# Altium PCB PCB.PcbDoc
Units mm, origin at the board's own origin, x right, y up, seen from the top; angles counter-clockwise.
Board outline 41 x 25.36 mm, 2 copper layers (TOP, BOTTOM), stack 1.586 mm thick; 38 components, 21 nets, 105 pads, 68 vias.
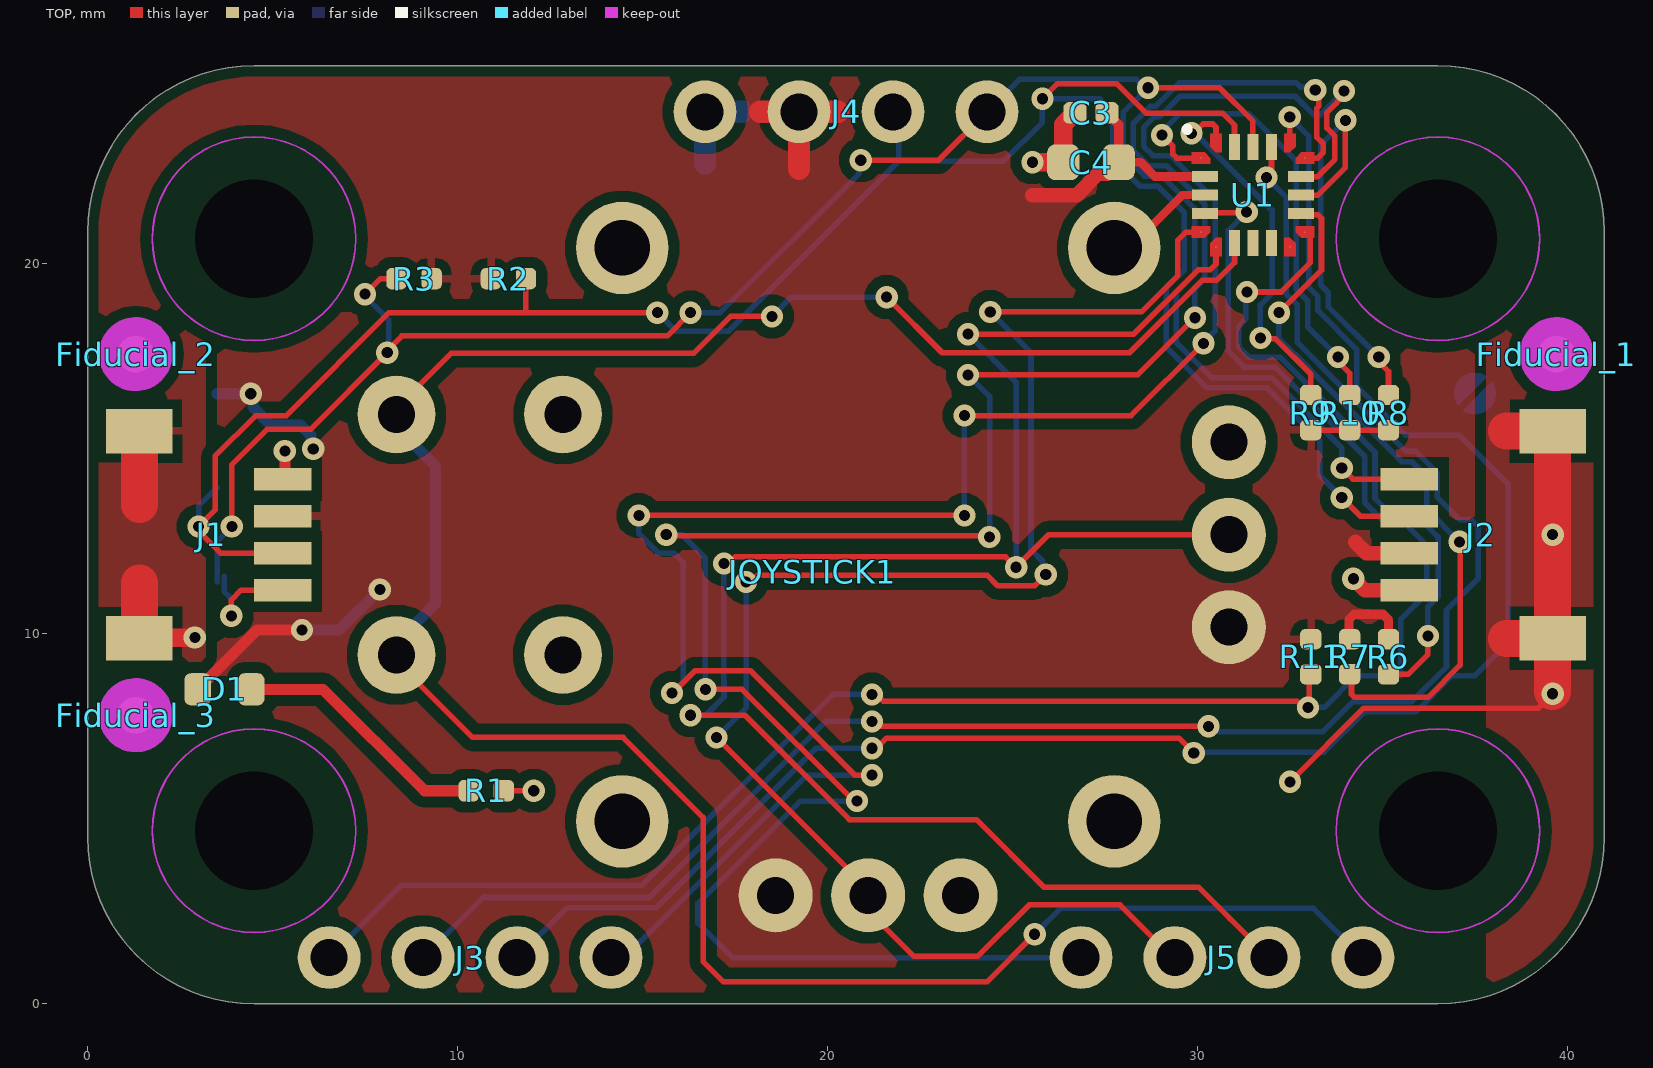
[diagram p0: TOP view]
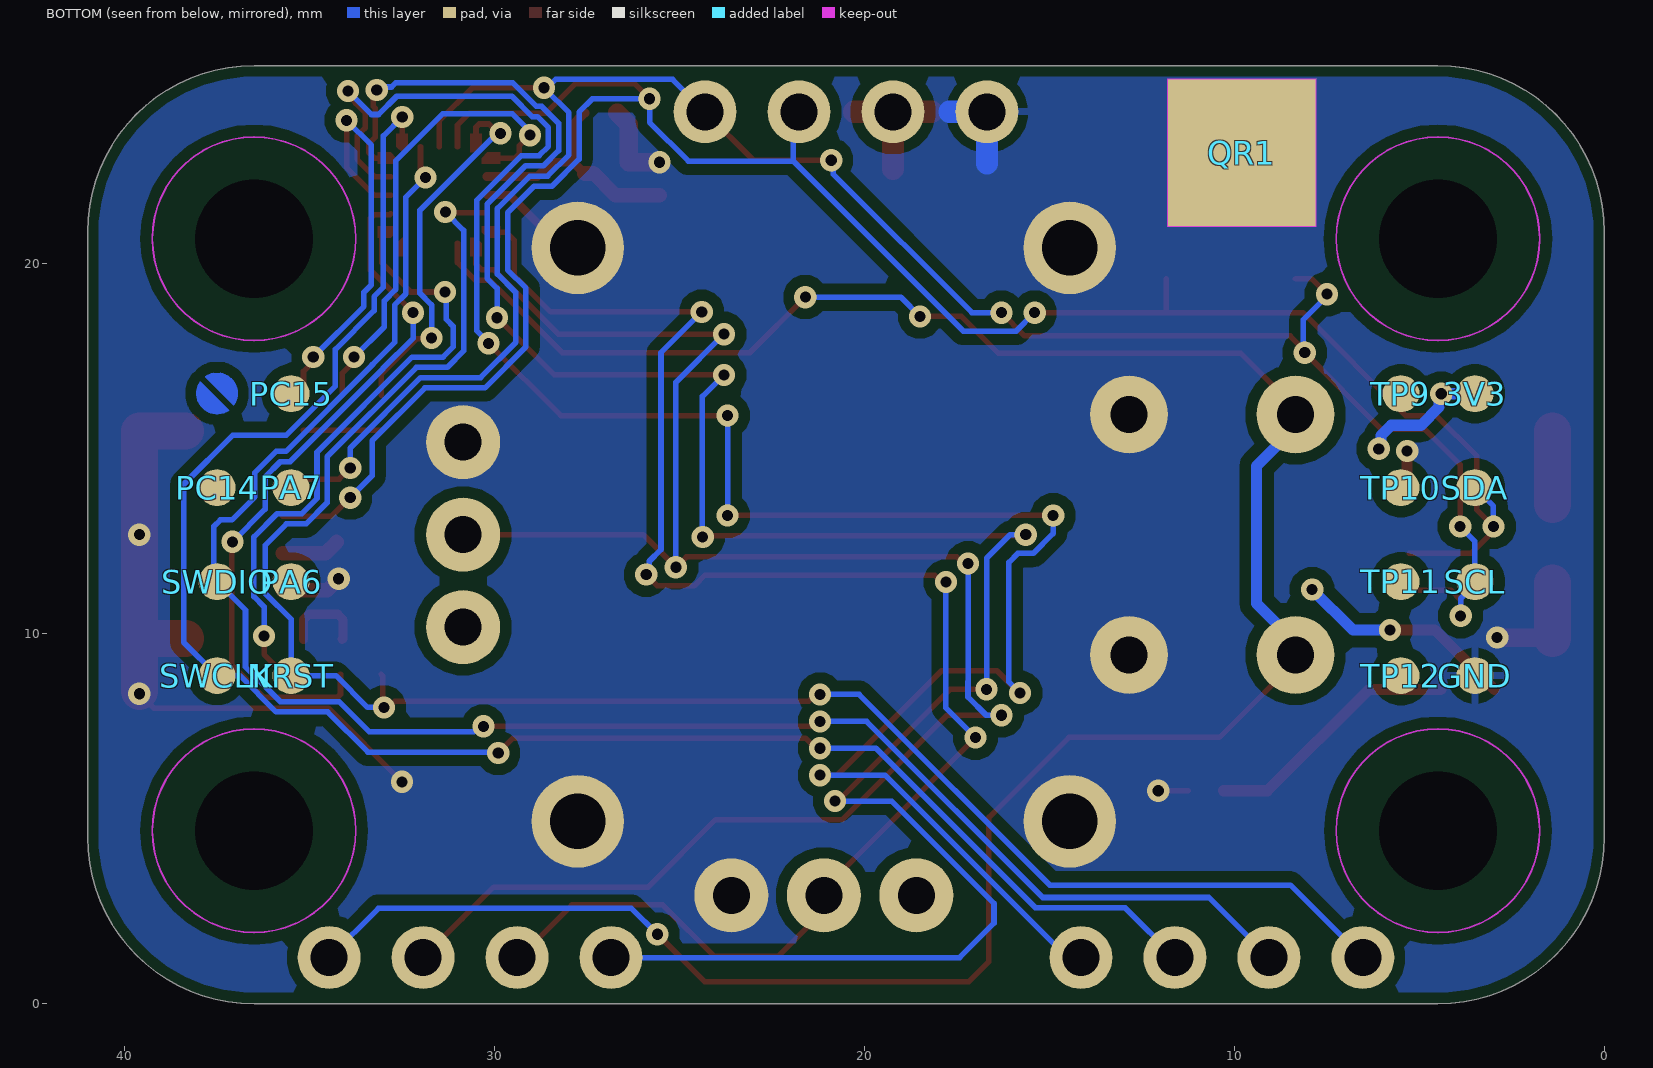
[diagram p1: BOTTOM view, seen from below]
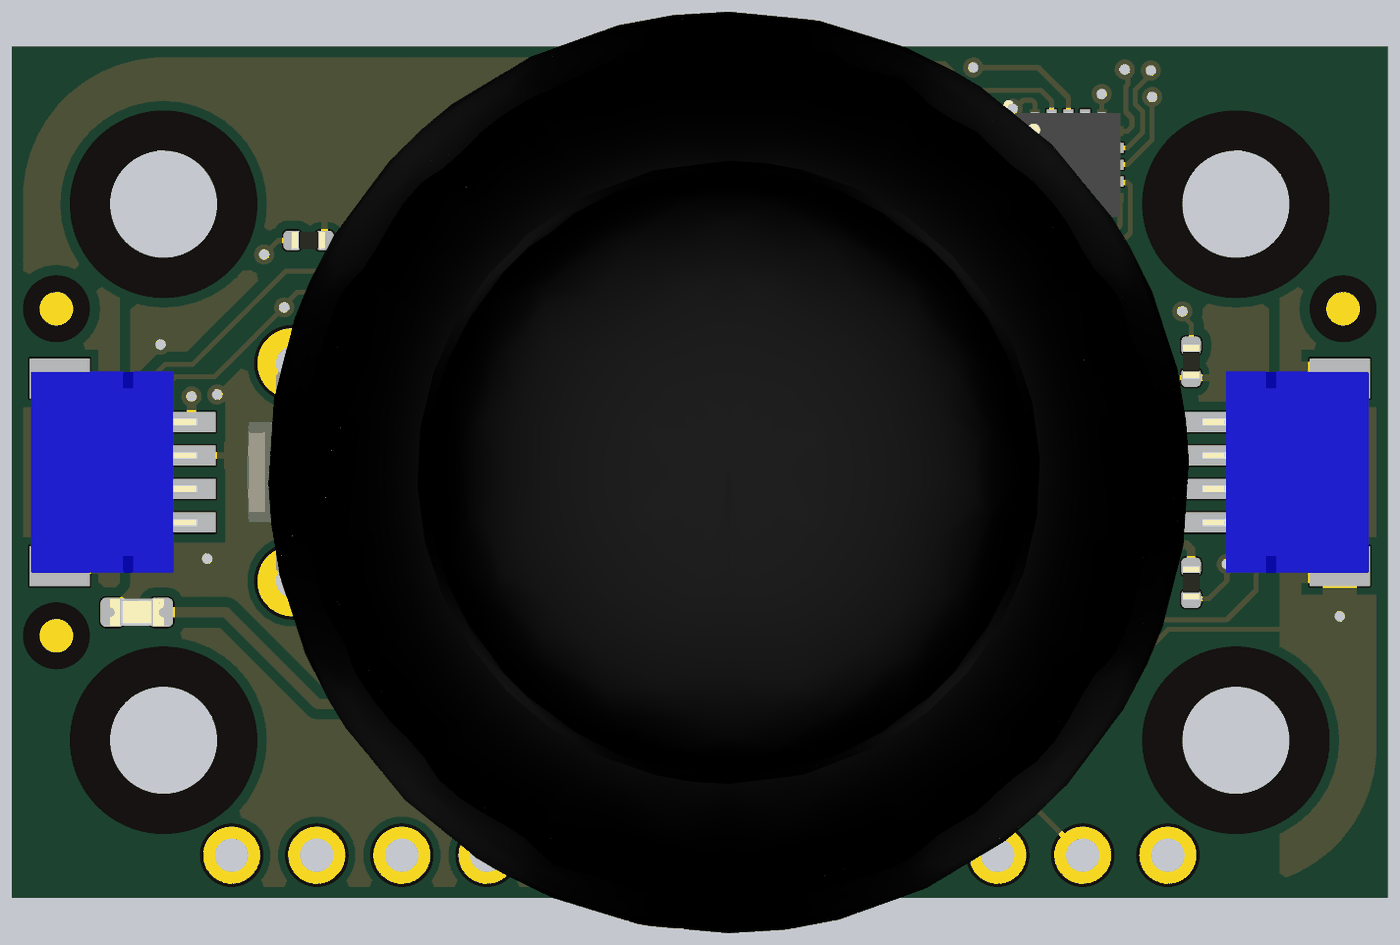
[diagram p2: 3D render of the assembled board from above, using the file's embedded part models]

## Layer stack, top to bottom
Top Solder: solder mask 0.01, Solder Resist, Dk 3.5
TOP: signal copper 0.018
Dielectric: core 1.55, FR-4, Dk 4.8
BOTTOM: signal copper 0.018
Bottom Solder: solder mask 0.01, Solder Resist, Dk 3.5

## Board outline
0,4.5 ccw(c4.5,4.5) 4.5,0 36.5,0 ccw(c36.5,4.5) 41,4.5 41,20.86 ccw(c36.5,20.86) 36.5,25.36 4.5,25.36 ccw(c4.5,20.86) 0,20.86

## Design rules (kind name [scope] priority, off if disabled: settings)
BoardOutlineClearance Mousebites [(ObjectKind = 'Pad') And (Name = 'Free-MOUSEBITE')] p1: gap=0 ignorepadtopadclearanceinfootprint=FALSE
BoardOutlineClearance Silks [(OnLayer('Top Overlay') OR OnLayer('Bottom Overlay'))] p2: gap=0 ignorepadtopadclearanceinfootprint=FALSE
BoardOutlineClearance [All] p3: gap=0.3 ignorepadtopadclearanceinfootprint=FALSE
Clearance COPPER_0.3mm [All] p1: gap=0.127 ignorepadtopadclearanceinfootprint=FALSE except(0.3: Arc-Fill Arc-Poly Arc-Region Track-Fill Track-Poly Track-Region SMDPad-Fill SMDPad-Poly SMDPad-Region THPad-Fill THPad-Poly THPad-Region Via-Fill Via-Poly Via-Region Fill-Fill Fill-Poly Fill-Region Poly-Poly Poly-Region Region-Region)
Clearance "Generic clearance 0.15mm" [All] p2: gap=0.15 ignorepadtopadclearanceinfootprint=FALSE
ComponentClearance [All] p1: gap=0.2 collisioncheckmode=3 verticalgap=0 showdistances=TRUE
DiffPairsRouting USB [InDifferentialPairClass('USB')] p1: maxlimit=0.15 minlimit=0.15 mostfreqgap=0.15 toplayer_minwidth=0.15 toplayer_maxwidth=0.21 toplayer_prefwidth=0.2 bottomlayer_minwidth=0.15 bottomlayer_maxwidth=0.21 bottomlayer_prefwidth=0.2 impedanceprofiledriven=TRUE impedanceprofileid={E6B00C31-4C8E-439C-824F-D2B2CDC26F9C} impedanceprofilevalue=90.000000 maxuncoupledlength=12.7
Height [All] p1: minheight=0 maxheight=30 prefheight=12.7
HoleSize [All] p1: absolutevalues=TRUE maxlimit=30 minlimit=0.3 maxpercent=80.000 minpercent=20.000
HoleToHoleClearance [All] p1: gap=0.25 allowstackedmicrovias=FALSE
MinimumAnnularRing [All] p1: minimumring=0.15
PlaneConnect [All] p1: pad.planeconnectstyle=Relief pad.reliefexpansion=0.508 pad.reliefentries=4 pad.reliefconductorwidth=0.254 pad.reliefairgap=0.254 via.planeconnectstyle=Direct via.reliefexpansion=0.508 via.reliefentries=4 via.reliefconductorwidth=0.254 via.reliefairgap=0.254
PolygonConnect PolygonConnect_QR [(ObjectKind = 'Pad') And (Name = 'QR1-PAD')] p1: connectstyle=Direct reliefconductorwidth=0.254 reliefentries=4 polygonreliefangle="90 Angle" airgapwidth=0.254
PolygonConnect [All] p2: thpad.connectstyle=Relief thpad.reliefconductorwidth=0.2 thpad.reliefentries=4 thpad.polygonreliefangle="90 Angle" thpad.airgapwidth=0.254 smdpad.connectstyle=Relief smdpad.reliefconductorwidth=0.2 smdpad.reliefentries=4 smdpad.polygonreliefangle="90 Angle" smdpad.airgapwidth=0.254 via.connectstyle=Direct via.reliefconductorwidth=0.254 via.reliefentries=4 via.polygonreliefangle="90 Angle" via.airgapwidth=0.254
RoomDefinition U_MICROCONTROLLER [InComponentClass('U_MICROCONTROLLER')] p1: confinementstyle=ConfineIn formatcopy=TRUE lockcomponents=FALSE outline -26.2,-22.88 24.6,-22.88 24.6,2.52 -26.2,2.52
RoomDefinition K36 [False vs False] p2: confinementstyle=ConfineIn formatcopy=TRUE lockcomponents=FALSE outline 12.1,25.6 15.4,25.6 15.4,22.8 12.1,22.8
RoomDefinition TOP [InComponentClass('TOP')] p3: confinementstyle=ConfineIn formatcopy=TRUE lockcomponents=FALSE outline 42.1,5.4 49.2,5.4 49.2,22.3 42.1,22.3
RoutingVias StandardVias [All] p1: holewidth=0.3 width=0.6 viastyle="Through Hole" minholewidth=0.3 minwidth=0.6 maxholewidth=0.3 maxwidth=0.6
SMDToCorner [All] p1: distance=39370
SilkToSilkClearance [All] p1: silktosilkclearance=0.2
SilkToSolderMaskClearance [IsPad] p1: minsilkscreentomaskgap=0.15 clearancetoexposedcopper=TRUE
SolderMaskExpansion VIAtented [IsVia] p1: expansion=0.102 istentingtop=TRUE
SolderMaskExpansion [All] p2: expansion=0.05 istentingtop=FALSE
SupplyNets "Schematic Supply Nets_1" [InNet('GND')] p1: voltage=0.000
SupplyNets "Schematic Supply Nets" [InNet('+3V3')] p2: voltage=0.000
UnConnectedPin [All] p1:
UnRoutedNet [NOT WithinRoom('K36')] p1: checkbadconnections=TRUE
ViasUnderSMD [All] p1: allowed=FALSE
Width StandardTraces [All] p1: maxlimit=5 minlimit=0.15 preferedwidth=0.15 minimp=50.000000 maximp=50.000000 favimp=50.000000
21 further rules are at their usual default settings.

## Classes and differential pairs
component class U_MICROCONTROLLER: C3 C4 R2 R3 R6 R7 R8 R9 R10 R11 U1
component class TOP: 3V3 D1 Fiducial_1 Fiducial_2 Fiducial_3 GND J1 J2 J3 J4 J5 JOYSTICK1 NRST PA6 PA7 PC14 PC15 QR1 R1 SCL SDA SWCLK SWDIO TP9 TP10 TP11 TP12

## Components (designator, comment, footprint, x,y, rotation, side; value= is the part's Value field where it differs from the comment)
3V3 "Test point 1.00mm" TP-1.00MM 3.5,16.49 r90 bottom
C3 "0402B104K160CT" CAP-0402 27.122,24.08 r180 top value=100nF
C4 "GRM188R61C475KAAJD" CAP-0603 27.122,22.746 r0 top value=4.7µF
D1 "HSMG-C190" LEDC1608X80N-AK 3.7,8.5 r180 top
Fiducial_1 "Fiducial mark 1mm" "Fiducial mark 1mm-Footprint-1" 39.7,17.56 r270 top
Fiducial_2 "Fiducial mark 1mm" "Fiducial mark 1mm-Footprint-1" 1.3,17.56 r270 top
Fiducial_3 "Fiducial mark 1mm" "Fiducial mark 1mm-Footprint-1" 1.3,7.8 r270 top
GND "Test point 1.00mm" TP-1.00MM 3.5,8.87 r90 bottom
J1 "SM04B-SRSS-TB(LF)(SN)" SM04B-SRSS-TB(LF)(SN)-Footprint-1 3.337,12.68 r90 top locked
J2 "SM04B-SRSS-TB(LF)(SN)" SM04B-SRSS-TB(LF)(SN)-Footprint-1 37.663,12.68 r270 top locked
J3 "HEADER TH 2.54mm VERT. 1x004POS" "PIN HEADER 2.54mm VERT. 1x4POS-Footprint-1" 10.34,1.25 r0 top
J4 "HEADER TH 2.54mm VERT. 1x004POS" "PIN HEADER 2.54mm VERT. 1x4POS-Footprint-1" 20.5,24.11 r0 top
J5 "HEADER TH 2.54mm VERT. 1x004POS" "PIN HEADER 2.54mm VERT. 1x4POS-Footprint-1" 30.66,1.25 r0 top
JOYSTICK1 "FJN10K-S1B10KD0N" FJN10K-S1B10KD0N 21.1,12.68 r0 top locked
NRST "Test point 1.00mm" TP-1.00MM 35.5,8.87 r180 bottom
PA6 "Test point 1.00mm" TP-1.00MM 35.5,11.41 r180 bottom
PA7 "Test point 1.00mm" TP-1.00MM 35.5,13.95 r180 bottom
PC14 "Test point 1.00mm" TP-1.00MM 37.5,13.95 r180 bottom
PC15 "Test point 1.00mm" TP-1.00MM 35.5,16.49 r180 bottom
QR1 "QR CODE 4x4mm" "QR CODE 4x4mm" 9.8,23 r180 bottom
R1 "CRCW04021K00FKEDC" RES-0402 10.775,5.76 r180 top value=1k
R2 "RC0402FR-074K7L" RES-0402 11.375,19.6 r180 top value=4.7k
R3 "RC0402FR-074K7L" RES-0402 8.825,19.6 r0 top value=4.7k
R6 "RC0402FR-074K7L" RES-0402 35.163,9.38 r270 top value=4.7k
R7 "RC0402FR-074K7L" RES-0402 34.113,9.38 r270 top value=4.7k
R8 "RC0402FR-074K7L" RES-0402 35.163,15.98 r90 top value=4.7k
R9 "RC0402FR-074K7L" RES-0402 33.063,15.98 r90 top value=4.7k
R10 "RC0402FR-074K7L" RES-0402 34.113,15.98 r90 top value=4.7k
R11 "RC0402FR-074K7L" RES-0402 33.063,9.38 r270 top value=4.7k
SCL "Test point 1.00mm" TP-1.00MM 3.5,11.41 r90 bottom
SDA "Test point 1.00mm" TP-1.00MM 3.5,13.95 r90 bottom
SWCLK "Test point 1.00mm" TP-1.00MM 37.5,8.87 r180 bottom
SWDIO "Test point 1.00mm" TP-1.00MM 37.5,11.41 r180 bottom
TP9 "Test point 1.00mm" TP-1.00MM 5.5,16.49 r0 bottom
TP10 "Test point 1.00mm" TP-1.00MM 5.5,13.95 r0 bottom
TP11 "Test point 1.00mm" TP-1.00MM 5.5,11.41 r0 bottom
TP12 "Test point 1.00mm" TP-1.00MM 5.5,8.87 r0 bottom
U1 "STM32C011F4U6TR" UFQFPN20 31.5,21.86 r0 top

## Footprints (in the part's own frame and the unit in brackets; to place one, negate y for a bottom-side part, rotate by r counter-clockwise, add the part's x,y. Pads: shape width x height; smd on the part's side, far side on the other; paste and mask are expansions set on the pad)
CAP-0402 [mm] "Chip Capacitor, 2-Leads, Body  0402 (in) 1005 (mm), IPC Medium Density"
  rrect52% 0.63x0.58 smd mask+0.05: 1(-0.435,0) 2(0.435,0)
  body extent -0.5,-0.25 0.5,0.25, height 0.5
CAP-0603 [mm] "Chip Capacitor, Body 0603 imperial,1.6x0.8mm, IPC High Density"
  rrect51% 0.87x0.97 smd mask+0.05: 1(-0.75,0) 2(0.75,0)
  body extent -0.8,-0.4 0.8,0.4, height 0.8
"Fiducial mark 1mm-Footprint-1" [mm]
  round 1 smd paste-10 mask+0.5: 1(0,0)
  TOP keep-out circle w1: c0,0 r0.5
FJN10K-S1B10KD0N [mm]
  round 2 hole 1 mask+0.1: 1(-2.5,-9.75) 2(0,-9.75) 3(2.5,-9.75) 4(9.75,-2.5) 5(9.75,0) 6(9.75,2.5)
  round 2.1 hole 1 mask+0.1: 7(-12.75,-3.25) 7(-12.75,3.25) 8(-8.25,-3.25) 8(-8.25,3.25)
  round 2.5 hole 1.5 mask+0.1: 9(-6.65,-7.75) 9(-6.65,7.75) 9(6.65,-7.75) 9(6.65,7.75)
  body extent -14.13,-13.76 14,13.74, height 33.25
LEDC1608X80N-AK [mm]
  rrect50% 0.72x0.87 smd: A(0.725,0) C(-0.725,0)
  body extent -0.8,-0.4 0.8,0.4, height 0.79
"PIN HEADER 2.54mm VERT. 1x4POS-Footprint-1" [mm]
  round 1.7 hole 1 mask+0.1: 1(-3.81,0) 2(-1.27,0) 3(1.27,0) 4(3.81,0)
"QR CODE 4x4mm" [mm]
  rect 4x4 smd paste-2539.97 mask+0.1: PAD(0,0)
  TOP keep-out region: -2,2 2,2 2,-2 -2,-2
RES-0402 [mm] "Chip Resistor, 2-Leads, Body  0402 (in) 1005 (mm), IPC Medium Density"
  rrect51% 0.55x0.58 smd mask+0.05: 1(-0.475,0) 2(0.475,0)
  body extent -0.5,-0.25 0.5,0.25, height 0.34
SM04B-SRSS-TB(LF)(SN)-Footprint-1 [mm]
  rect 0.6x1.55 smd mask+0.05: 1(1.5,-1.937) 2(0.5,-1.937) 3(-0.5,-1.937) 4(-1.5,-1.937)
  rect 1.2x1.8 smd mask+0.05: FIX(-2.8,1.938) FIX(2.8,1.938)
  body extent -3,-2.16 3,2.8, height 2.98
TP-1.00MM [mm]
  rrect100% 1x1 smd paste-2.54: X(0,0)
UFQFPN20 [mm] "QFN, 20-Leads, Body 3.00x3.00mm, Pitch 0.50mm, IPC Medium Density"
  round 0.025 smd mask+0.05: 1(-1.4,1) 5(-1.4,-1) 6(-1,-1.4) 10(1,-1.4) 11(1.4,-1) 15(1.4,1) 16(1,1.4) 20(-1,1.4)
  rect 0.7x0.3 smd mask+0.05: 2(-1.3,0.5) 3(-1.3,0) 4(-1.3,-0.5) 12(1.3,-0.5) 13(1.3,0) 14(1.3,0.5)
  rect 0.3x0.7 smd mask+0.05: 7(-0.5,-1.3) 8(0,-1.3) 9(0.5,-1.3) 17(0.5,1.3) 18(0,1.3) 19(-0.5,1.3)
  TOP region: 1.65,-0.85 1.65,-1.15 1.3,-1.15 1.15,-1 1.15,-0.85
  TOP region: -1.15,1.3 -1,1.15 -0.85,1.15 -0.85,1.65 -1.15,1.65
  TOP region: -1.15,1 -1.15,0.85 -1.65,0.85 -1.65,1.15 -1.3,1.15
  TOP region: 1,1.15 0.85,1.15 0.85,1.65 1.15,1.65 1.15,1.3
  TOP region: 1.65,1.15 1.65,0.85 1.15,0.85 1.15,1 1.3,1.15
  TOP region: 1.15,-1.65 0.85,-1.65 0.85,-1.15 1,-1.15 1.15,-1.3
  TOP region: -0.85,-1.65 -1.15,-1.65 -1.15,-1.3 -1,-1.15 -0.85,-1.15
  TOP region: -1.3,-1.15 -1.15,-1 -1.15,-0.85 -1.65,-0.85 -1.65,-1.15
  silkscreen extent -1.8,1.75 -1.75,1.8, body extent -1.55,-1.55 1.55,1.55, height 0.6

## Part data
3V3 GND NRST PA6 PA7 PC14 PC15 SCL SDA SWCLK SWDIO TP9 TP10 TP11 TP12: library part UT0013-A.6, Manufacturer="This is not a component"
C3: library part C0012-A.15, "CAP CHIP 0402 100nF 10% 16V X7R", Case Code (Imperial)=0402, Dielectric=X7R, Manufacturer=Walsin, Tolerance=10%, Voltage=16V
C4: library part C0054-A.16, "CAP CHIP 0603 4.7uF 10% 16V X5R", Case Code (Imperial)=0603, Dielectric=X5R, Manufacturer=Murata, Manufacturer 3="Samsung Electro-Mechanics", Part number 2=GRM188R61C475KE11D, Part number 3=CL10A475KO8NNNC, Tolerance=10%, Voltage=16V
D1: library part L0009-A.5, "LED SMD 0603 GREEN/568 15mcd 120^", Manufacturer=Broadcom
Fiducial_1 Fiducial_2 Fiducial_3: library part UT0023-A.7, "Fiducial mark 1mm clearance 2mm"
J1 J2: library part J0005-A.2, "CONN JST 4POS SIDE 1MM TIN QWIIC", Manufacturer=JST
J3 J4 J5: library part J0162-A.6
JOYSTICK1: library part S0066-A.4, "Joystick 10kR 20%, max 5V, with switch 12V 50mA max 100mR", Manufacturer="FAVOR ELECTRONICS(DONG GUAN)CO., LTD."
QR1: library part QR-0001-A.5, "QR CODE 4x4mm on layer 34 (This is not a component)", Manufacturer="This is not a component"
R1: library part R0007-A.24, "RES CHIP 0402 1k 1% 1/16W", Case Code (Imperial)=0402, Manufacturer=Vishay, Power=62.5mW, Temperature Coefficient=100ppm, Tolerance=1%
R2 R3 R6 R7 R8 R9 R10 R11: library part R0013-A.24, "RES CHIP 0402 4k7 1% 1/16W", Case Code (Imperial)=0402, Manufacturer=YAGEO, Power=62.5mW, Temperature Coefficient=200ppm, Tolerance=1%
U1: library part U0363-A.4, "IC Cortex M0, 32b MCU, 16KB Flash, 6KB RAM, VDD 2-3.6V, -40°C to 85°C, QFN20 3x3mm", Manufacturer="ST Microelectronics"

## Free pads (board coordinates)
  round 3 hole 3.2 unplated paste-2539.97 mask+1.3: MH(4.5,4.68) MH(4.5,20.68) MH(36.5,4.68) MH(36.5,20.68)

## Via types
v1: diameter 0.6, hole 0.3, TOP to BOTTOM, tented both sides, 68 vias

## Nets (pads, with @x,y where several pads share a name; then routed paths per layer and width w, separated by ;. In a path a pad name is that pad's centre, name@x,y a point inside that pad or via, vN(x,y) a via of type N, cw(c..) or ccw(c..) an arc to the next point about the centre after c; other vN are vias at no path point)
+3V3: 3V3.X C3.1 C4.2 D1.A J1.2 J2.2 J4.2 JOYSTICK1.1 JOYSTICK1.4 R2.2 R3.2 R6.1 R7.1 R8.1 R9.1 R10.1 R11.1 U1.2 | length 25.9
  TOP w0.15: R9.1 R10.1 R8.1
  TOP w0.24: C4.2@27.57,22.444 C4.2 28.465,22.746 28.851,22.36 U1.2
  TOP w0.25: C3.1 27.568,24.08 27.747,23.901 27.747,23.89 27.872,23.765 C4.2 ; R7.1 34.093,9.875 34.093,10.381 34.239,10.528 35.017,10.528 35.163,10.381 R6.1
  TOP w0.3: D1.A 4.575,10.1 v1(5.8,10.1)
  TOP w0.4: 25.537,21.856 26.734,21.856 27.322,22.444 C4.2@27.57,22.444 ; 34.27,12.48 34.569,12.18 J2.2
  TOP w0.6: 18.18,24.11 J4.2 ; 19.23,22.57 J4.2 ; 20.28,24.11 J4.2
  BOTTOM w0.3: 3V3.X v1(4.41,16.49) 4.467,16.433 4.467,16.127 4.957,15.637 5.763,15.637 6.043,15.357 6.043,15.057 v1(6.1,15) ; v1(5.8,10.1) 6.8,10.1 v1(7.9,11.2)
GND: C3.2 C4.1 GND.X J1.1 J1.FIX J2.1 J2.FIX J4.1 JOYSTICK1.3 JOYSTICK1.6 JOYSTICK1.8 JOYSTICK1.9 QR1.PAD R1.1 U1.3 | length 33.6
  TOP w0.15: R1.1 v1(12.06,5.76) ; v1(32.5,6) 34.491,7.991 39.211,7.991 v1(39.6,8.38)
  TOP w0.22: JOYSTICK1.9@27.75,20.43 28.162,20.43 29.592,21.86 U1.3
  TOP w0.3: J1.1 5.332,14.238 v1(5.332,14.942)
  TOP w0.4: v1(34.213,11.49) 34.523,11.18 J2.1
  TOP w0.5: J1.FIX@1.399,9.88 1.419,9.9 v1(2.9,9.9) ; v1(25.543,22.746) C4.1 26.372,23.765 26.507,23.9 26.507,23.903 26.684,24.08 C3.2
  TOP w1: J1.FIX@1.399,9.88 1.399,11.379 ; 1.399,13.499 J1.FIX@1.399,15.48 ; 38.353,9.88 J2.FIX@39.601,9.88 ; 38.353,15.48 39.601,15.48 v1(39.601,12.68) J2.FIX@39.601,9.88 ; v1@39.601,8.443 J2.FIX@39.601,9.88
  BOTTOM w0.6: 16.69,22.71 J4.1 17.7,24.11
NetD1_C: D1.C R1.2 | length 7
  TOP w0.3: D1.C 6.362,8.5 9.102,5.76 R1.2
NetU1_8: U1.8
NetU1_9: U1.9
NetU1_10: U1.10
PA0_1: J5.2 JOYSTICK1.2 U1.5 | length 44.3
  TOP w0.15: v1(17,7.2) 20.922,3.278 21.1,3.278 21.1,2.52 22.34,1.28 24.058,1.28 25.452,2.674 27.906,2.674 29.33,1.25 J5.2 ; v1(17.8,11.4) 17.922,11.4 18.1,11.578 24.322,11.578 24.602,11.298 25.598,11.298 v1(25.9,11.6) ; v1(24.4,18.7) 28.486,18.7 29.468,19.682 29.468,20.644 29.684,20.86 U1.5
  BOTTOM w0.15: v1(17,7.2) 17.8,8 v1(17.8,11.4) ; v1(24.4,18.7) 25.5,17.6 25.5,12.28 25.819,11.961 25.819,11.681 v1(25.9,11.6)
PA1_1: J5.3 JOYSTICK1.5 U1.6 | length 52.2
  TOP w0.15: v1(16.3,7.8) 17.77,7.8 20.592,4.978 24.022,4.978 25.845,3.155 30.026,3.155 30.878,2.302 J5.3 ; v1(17.2,11.9) 17.322,11.9 17.502,12.08 24.814,12.08 25.094,11.8 v1(25.1,11.8) 25.98,12.68 JOYSTICK1.5@30.96,12.68 ; v1(23.8,18.1) 28.277,18.1 30.016,19.838 30.342,19.838 30.5,19.997 U1.6
  BOTTOM w0.15: v1(16.3,7.8) 16.71,7.8 17.202,8.292 17.202,8.708 17.2,8.71 v1(17.2,11.9) ; v1(23.8,18.1) 25.1,16.8 v1(25.1,11.8)
PA2_1: J5.4 JOYSTICK1.7 U1.7 | length 67.5
  TOP w0.15: JOYSTICK1.7@8.1,9.505 8.416,9.189 10.405,7.2 14.476,7.2 16.64,5.036 16.64,1.14 17.18,0.6 24.32,0.6 v1(25.6,1.88) ; JOYSTICK1.7@8.1,15.855 9.825,17.58 16.38,17.58 17.38,18.58 v1(18.5,18.58) ; v1(21.6,19.1) 23.102,17.598 28.167,17.598 30.131,19.561 30.525,19.561 31,20.036 U1.7
  BOTTOM w0.15: v1(18.5,18.58) 19.02,19.1 v1(21.6,19.1) ; v1(25.6,1.88) 26.3,2.58 33.14,2.58 J5.4
  BOTTOM w0.3: JOYSTICK1.7@8.1,9.519 9.4,10.819 9.4,14.541 8.1,15.841 JOYSTICK1.7@8.1,15.855
PA6_2: R6.2 U1.11 | length 17.3
  TOP w0.15: v1(31.34,19.239) 32.259,19.239 33.045,20.025 33.045,20.772 32.957,20.86 U1.11 ; R6.2@35.263,8.905 35.692,8.905 36.229,9.441 v1(36.229,9.939)
  BOTTOM w0.15: v1(31.34,19.239) 31.302,19.202 31.302,18.499 31.118,18.314 31.118,17.755 31.393,17.48 32.226,17.48 34.798,14.908 34.798,13.659 35.209,13.248 35.873,13.248 36.504,12.617 36.504,11.008 36.229,10.732 v1(36.229,9.939)
PA7_2: R7.2 U1.12 | length 19.2
  TOP w0.15: v1(32.2,18.68) 33.352,19.832 33.352,21.228 33.25,21.33 32.83,21.33 U1.12 ; R7.2@34.163,8.905 34.163,8.368 34.251,8.28 36.226,8.28 37.1,9.154 37.1,12.473 v1(37.086,12.487)
  BOTTOM w0.15: v1(32.2,18.68) 32.2,18.21 32.202,18.208 32.202,17.988 33.021,17.169 33.021,17.157 35.526,14.652 35.791,14.652 36.202,14.241 36.202,13.371 v1(37.086,12.487)
PA8_2: R8.2 U1.13 | length 11.2
  TOP w0.15: U1.13 33.256,21.86 33.99,22.593 v1@33.99,23.87 ; v1(34.9,17.48) 34.9,17.358 35.163,17.095 R8.2
  BOTTOM w0.15: v1(34,23.88) 33.329,23.209 33.329,19.436 33.533,19.232 33.533,18.849 v1(34.9,17.48) v1(34.9,17.48)
PA9_USART1_TX_1: J3.4 U1.14 | length 56.9
  TOP w0.15: v1(14.9,13.2) v1(23.7,13.2) ; v1(15.8,8.4) 15.817,8.4 16.419,9.002 17.914,9.002 20.736,6.18 v1(21.2,6.18) ; v1(23.7,15.9) 28.208,15.9 v1(30.16,17.852) ; U1.14 33.25,22.36 33.713,22.823 33.713,23.457 33.498,23.672 33.498,24.088 33.722,24.312 33.758,24.348 33.758,24.36 33.961,24.562 v1(33.961,24.673)
  BOTTOM w0.15: J3.4 14.519,1.25 19.449,6.18 v1(21.2,6.18) ; v1(14.9,13.2) 14.9,12.712 15.434,12.178 15.852,12.178 16.1,11.93 16.1,8.7 v1(15.8,8.4) ; v1(23.7,13.2) v1(23.7,15.9) ; v1(30.16,17.852) 30.16,17.876 30.475,18.19 30.475,21.725 29.272,22.928 28.792,22.928 28.543,23.177 28.543,23.686 28.838,23.981 28.984,23.981 29.533,24.53 32.643,24.53 33.136,24.037 33.325,24.037 v1(33.961,24.673)
PA10_USART1_RX_1: J5.1 U1.15 | length 61.4
  TOP w0.15: v1(15.642,12.68) 15.673,12.649 24.343,12.649 v1(24.374,12.619) ; v1(16.7,8.5) 17.691,8.5 20.711,5.48 v1(20.8,5.48) ; v1(23.8,17) 28.385,17 v1(29.929,18.545) ; U1.15 33.25,22.86 33.4,23.01 33.4,23.248 33.221,23.427 33.221,24.203 33.28,24.262 33.28,24.481 33.184,24.577 v1(33.184,24.699)
  BOTTOM w0.15: v1(15.642,12.68) 16.06,12.68 16.698,12.042 16.698,8.502 v1(16.7,8.5) ; v1(20.8,5.48) 19.269,5.48 16.5,2.711 16.5,2.18 17.43,1.25 J5.1 ; v1(23.8,17) 24.38,16.42 24.38,12.625 v1(24.374,12.619) ; v1(29.929,18.545) 29.929,19.337 30.198,19.606 30.198,21.61 29.157,22.651 28.677,22.651 28.266,23.062 28.266,23.8 28.724,24.258 28.87,24.258 29.512,24.9 32.665,24.9 32.784,24.781 33.102,24.781 v1(33.184,24.699)
PA13_SWDIO_1: J3.3 SWCLK.X U1.16 | length 48.9
  TOP w0.15: v1(21.2,6.907) 21.322,6.907 21.595,7.18 29.5,7.18 v1(29.9,6.78) ; v1@32.444,24.019 v1(32.495,23.968) 32.5,23.963 U1.16
  BOTTOM w0.15: J3.3 12.957,2.597 15.382,2.597 19.693,6.907 v1(21.2,6.907) ; v1(29.9,6.78) 29.922,6.802 33.422,6.802 34.511,7.891 35.906,7.891 36.885,8.87 SWCLK.X 38.4,9.77 38.4,14.043 37.074,15.369 35.628,15.369 34.302,16.695 34.302,17.688 33.256,18.734 33.256,19.117 33.002,19.371 33.002,23.461 v1(32.495,23.968)
PA14_SWCLK_BOOT0_1: J3.2 SWDIO.X U1.17 | length 48.3
  TOP w0.15: v1(21.2,7.634) 21.322,7.634 21.456,7.5 v1(30.3,7.5) ; v1(31.867,22.336) 31.867,22.429 32,22.562 U1.17
  BOTTOM w0.15: J3.2 10.694,2.874 15.183,2.874 19.943,7.634 v1(21.2,7.634) ; v1(30.3,7.5) 30.422,7.5 30.565,7.357 33.39,7.357 34.201,8.168 35.791,8.168 36.731,9.108 36.731,10.641 37.588,11.498 37.588,12.279 37.588,12.904 37.412,13.08 37.097,13.08 36.479,13.698 36.479,14.356 35.906,14.929 35.641,14.929 33.298,17.272 33.298,17.284 32.702,17.88 32.702,18.888 32.398,19.192 32.398,21.805 v1(31.867,22.336)
PC14_2: R9.2 U1.20 | length 10.2
  TOP w0.15: v1(29.838,23.528) 29.899,23.528 30.151,23.781 30.412,23.781 30.5,23.693 U1.20 ; v1(31.7,18) 31.72,17.98 32.1,17.98 33.063,17.017 R9.2
  BOTTOM w0.15: v1(29.838,23.528) 29.94,23.528 32.021,21.447 32.021,19.211 31.698,18.888 31.698,18.002 v1(31.7,18)
PC15_2: R10.2 U1.1 | length 12.8
  TOP w0.15: v1(29.045,23.478) 29.336,23.187 29.336,22.966 29.442,22.86 U1.1 ; v1(33.8,17.48) 33.8,17.358 34.113,17.045 R10.2
  BOTTOM w0.15: v1(29.045,23.478) 29.045,23.582 29.523,24.06 31.398,24.06 32.675,22.783 32.675,19.306 32.979,19.003 32.979,18.301 v1(33.8,17.48)
PF2_N\R\S\T\_1: J3.1 NRST.X R11.2 U1.4 | length 50.5
  TOP w0.15: v1(21.2,8.361) 21.322,8.361 21.503,8.18 32.694,8.18 32.863,8.011 v1(32.985,8.011) 33.024,8.05 33.024,8.866 R11.2 ; U1.4 30.22,21.38 31.31,21.38 v1(31.33,21.4)
  BOTTOM w0.15: J3.1 8.487,3.207 14.993,3.207 20.147,8.361 v1(21.2,8.361) ; v1(31.33,21.4) 30.836,20.906 30.836,17.645 31.278,17.203 32.111,17.203 34.521,14.793 34.521,13.544 35.095,12.971 35.623,12.971 36.202,12.392 36.202,11.097 35.5,10.395 NRST.X 34.29,8.87 33.431,8.011 v1(32.985,8.011)
SCL_1: J1.4 J2.4 J4.4 R3.1 SCL.X U1.18 | length 59.2
  TOP w0.15: v1(3.886,10.486) 3.886,10.916 4.15,11.18 J1.4 ; v1(3.9,12.9) 3.9,14.573 4.862,15.535 6.035,15.535 v1(8.1,17.6) 8.1,17.656 8.496,18.052 15.672,18.052 v1(16.3,18.68) ; v1(7.5,19.18) 7.92,19.6 R3.1 ; v1(20.9,22.8) 23,22.8 J4.4 ; v1(28.662,24.76) 30.601,24.76 31.5,23.861 U1.18 ; v1(33.9,14.48) 34.2,14.18 J2.4
  BOTTOM w0.15: SCL.X 3.5,12.5 v1(3.9,12.9) ; SCL.X@3.694,11.557 3.694,11.14 3.886,10.948 v1(3.886,10.486) ; v1(7.5,19.18) 7.5,19.128 8.144,18.484 8.144,17.644 v1(8.1,17.6) ; v1(16.3,18.68) 17.1,18.68 20.839,22.419 20.839,22.739 v1(20.9,22.8) ; J4.4 25.184,24.984 28.349,24.984 28.573,24.76 v1(28.662,24.76) 28.617,24.716 27.989,24.087 27.989,22.948 28.563,22.374 29.043,22.374 29.921,21.496 29.921,19.721 29.427,19.227 29.427,17.875 30.376,16.926 31.996,16.926 33.9,15.022 v1(33.9,14.48)
SDA_1: J1.3 J2.3 J4.3 R2.1 SDA.X U1.19 | length 60.6
  TOP w0.15: J1.3 3.598,12.18 3.186,12.592 3,12.778 v1(3,12.9) 3.448,13.348 3.448,14.801 4.547,15.9 5.372,15.9 8.152,18.68 11.3,18.68 v1(15.4,18.68) ; R2.1 11.85,18.73 11.9,18.68 ; v1(25.808,24.462) 26.22,24.874 27.809,24.874 28.61,24.073 30.676,24.073 31,23.748 U1.19 ; v1(33.9,13.68) 34.4,13.18 J2.3
  BOTTOM w0.15: v1(3,12.9) 3,13.45 SDA.X ; v1(15.4,18.68) 15.902,18.178 17.328,18.178 21.355,22.205 21.926,22.776 ; J4.3 21.926,23.954 21.926,22.776 ; v1(33.9,13.68) 33.306,14.274 33.306,15.225 31.882,16.649 30.262,16.649 29.15,17.76 29.15,19.342 29.644,19.835 29.644,21.381 28.928,22.097 28.448,22.097 27.712,22.833 27.712,24.103 27.353,24.462 v1(25.808,24.462) 25.808,23.822 24.762,22.776 21.926,22.776
pads on no net: Fiducial_1.1 Fiducial_2.1 Fiducial_3.1 PA6.X PA7.X PC14.X PC15.X TP9.X TP10.X TP11.X TP12.X

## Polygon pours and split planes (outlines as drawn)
+3V3 on TOP "NONET_L04_P-001" (solid, remove dead copper, pour order 8): 0,4.5 ccw(c4.5,4.5) 4.5,0 36.5,0 ccw(c36.5,4.5) 41,4.5 41,20.86 ccw(c36.5,20.86) 36.5,25.36 4.5,25.36 ccw(c4.5,20.86) 0,20.86
GND on TOP "NONET_L04_P-001" (solid, remove dead copper, pour order 5): 0,25.36 0,0 3.2,0 3.2,25.36
GND on TOP "NONET_L04_P-001" (solid, remove dead copper, pour order 6): 41,25.36 41,0 37.8,0 37.8,25.36
GND on BOTTOM "NONET_L04_P-001" (solid, remove dead copper, pour order 9): 0,4.5 ccw(c4.5,4.5) 4.5,0 36.5,0 ccw(c36.5,4.5) 41,4.5 41,20.86 ccw(c36.5,20.86) 36.5,25.36 4.5,25.36 ccw(c4.5,20.86) 0,20.86

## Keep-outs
Keep-Out Layer:
  circle w0.05: c36.5,4.68 r2.75
  circle w0.05: c36.5,20.68 r2.75
  circle w0.05: c4.5,4.68 r2.75
  circle w0.05: c4.5,20.68 r2.75

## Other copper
BOTTOM:
  region: 389 vertices and 0 holes, not listed, extent 36.945,16.174 37.825,17.054
  region: 403 vertices and 0 holes, not listed, extent 37.177,15.936 38.056,16.815

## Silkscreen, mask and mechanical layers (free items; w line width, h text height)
Route Tool Path:
  lines w2: -1,8.498 -1,16.86 ; 42,4.5 cw(c36.5,4.5) 36.5,-1 ; 42,8.498 42,16.86 ; -1,4.498 cw(c0,4.5) -1,4.5 ccw(c4.5,4.5) -1,4.498 ; -1,4.498 ccw(c4.5,4.5) 4.498,-1 ; -1,20.86 cw(c4.5,20.86) 4.5,26.36 ; -1,20.86 -1,20.86 ; 4.498,-1 ccw(c4.5,0) 4.5,-1 ; 4.498,-1 ccw(c4.5,4.5) 4.5,-1 ; 4.5,-1 36.5,-1 ; 4.5,26.36 4.5,26.36 ; 4.5,26.36 36.5,26.36 ; 36.5,-1 36.5,-1 ; 36.5,26.36 cw(c36.5,25.36) 36.502,26.36 ; 36.5,26.36 cw(c36.5,20.86) 36.502,26.36 ; 36.502,26.36 cw(c36.5,20.86) 42,20.863 ; 42,20.863 cw(c36.5,20.86) 42,20.86 ccw(c41,20.86) 42,20.863
Board:
  the board outline again, w0.05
